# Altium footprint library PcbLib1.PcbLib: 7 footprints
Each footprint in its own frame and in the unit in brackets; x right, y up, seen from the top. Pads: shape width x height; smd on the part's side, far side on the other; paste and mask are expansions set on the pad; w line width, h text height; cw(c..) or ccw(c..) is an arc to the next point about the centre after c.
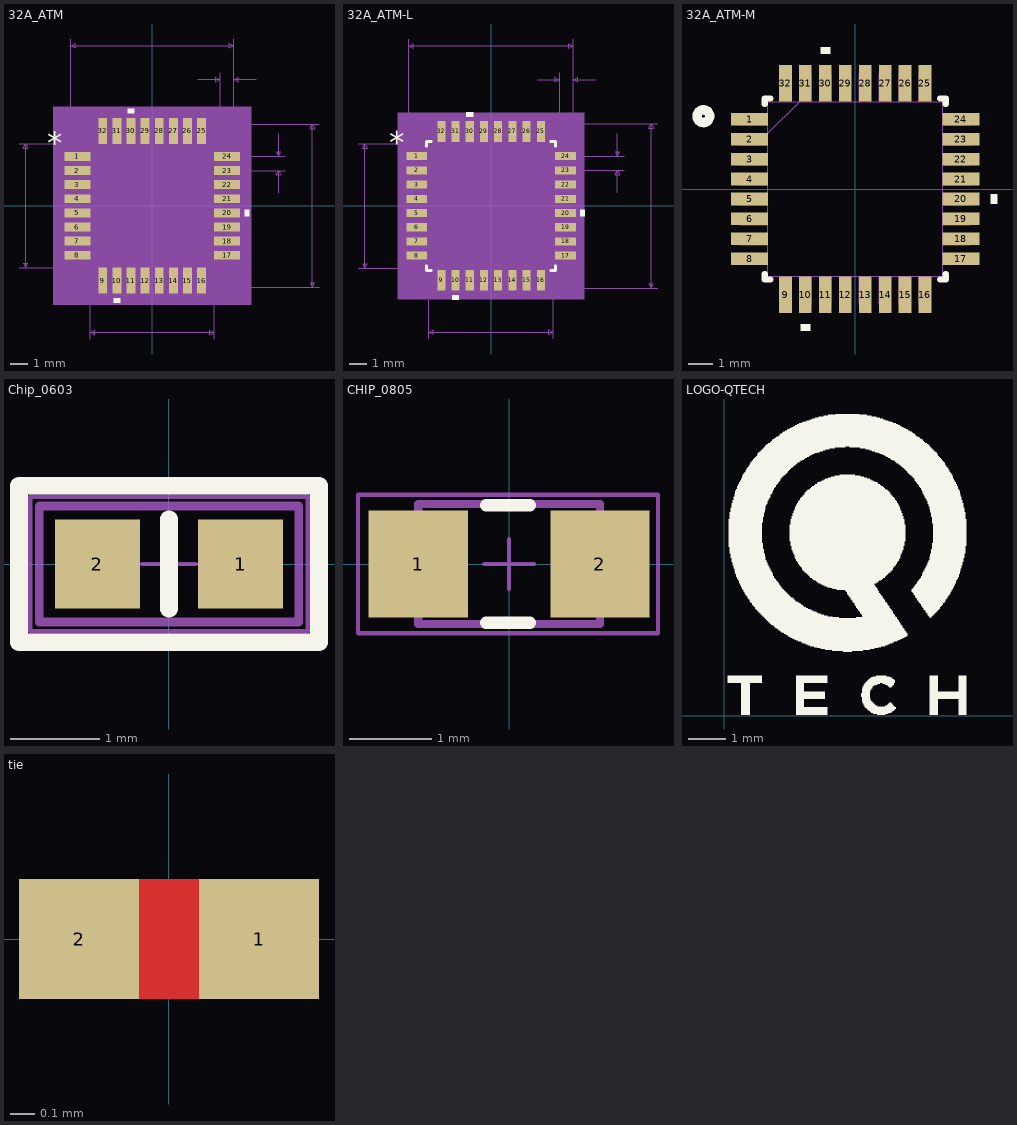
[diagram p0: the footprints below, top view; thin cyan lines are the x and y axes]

## 32A_ATM [mil]
pads (32):
  rect 58x20 smd paste+0 mask+0: 1(-167,110.24) 2(-167,78.74) 3(-167,47.24) 4(-167,15.75) 5(-167,-15.75) 6(-167,-47.24) 7(-167,-78.74) 8(-167,-110.24) 17(167,-110.24) 18(167,-78.74) 19(167,-47.24) 20(167,-15.75) 21(167,15.75) 22(167,47.24) 23(167,78.74) 24(167,110.24)
  rect 20x58 smd paste+0 mask+0: 9(-110.24,-167) 10(-78.74,-167) 11(-47.24,-167) 12(-15.75,-167) 13(15.75,-167) 14(47.24,-167) 15(78.74,-167) 16(110.24,-167) 25(110.24,167) 26(78.74,167) 27(47.24,167) 28(15.75,167) 29(-15.75,167) 30(-47.24,167) 31(-78.74,167) 32(-110.24,167)
Top Overlay:
  region: -71.24,-206 -86.24,-206 -86.24,-216 -71.24,-216
  region: 206,-8.25 216,-8.25 216,-23.25 206,-23.25
  region: -39.74,206 -54.74,206 -54.74,216 -39.74,216
  text "*" at -233.5,115.98 h50
Mechanical 5:
  region: 221,-221 -221,-221 -221,221 221,221
Mechanical 7:
  lines w1: -297,-138 -110.24,-138 ; -297,138 -110.24,138 ; -182,110.24 -182,372 ; -138,-297 -138,-110.24 ; 102,282 152,282 ; 110.24,-182 372,-182 ; 110.24,182 372,182 ; 138,-297 138,-110.24 ; 152,110.24 152,297 ; 167,78.74 297,78.74 ; 167,110.24 297,110.24 ; 182,297 182,110.24 182,372 ; 232,282 182,282 ; 282,28.74 282,78.74 ; 282,160.24 282,110.24 ; -282,-138 -282,138 ; -282,-138 -287,-128 -277,-128 -282,-138 ; -282,138 -287,128 -277,128 -282,138 ; -182,357 182,357 ; -182,357 -172,362 -172,352 -182,357 ; -138,-282 138,-282 ; -138,-282 -128,-277 -128,-287 -138,-282 ; 138,-282 128,-277 128,-287 138,-282 ; 152,282 142,287 142,277 152,282 ; 182,282 192,287 192,277 182,282 ; 182,357 172,362 172,352 182,357 ; 282,78.74 277,68.74 287,68.74 282,78.74 ; 282,110.24 277,120.24 287,120.24 282,110.24 ; 357,-182 357,182 ; 357,-182 352,-172 362,-172 357,-182 ; 357,182 352,172 362,172 357,182
  text "Default Horiz Padstyle: RX20Y58D0T" at -425,-457 h50
  text "Default Vert Padstyle: RX20Y58D0T" at -412.5,-507 h50
  text "0.031in/0.8mm" at 302,81.99 h25
  text "0.03in/0.762mm" at 79.5,302 h25
  text "0.364in/9.246mm" at -93.75,377 h25
  text "0.364in/9.246mm" at 377,-12.5 h25
  text "0.276in/7.01mm" at -87.5,-327 h25
  text "0.276in/7.01mm" at -477,-12.5 h25
Mechanical 13:
  lines w1: -138,88 -88,138 ; -182,-119.24 -182,-101.24 -138,-101.24 -138,-119.24 -182,-119.24 ; -182,-87.74 -182,-69.74 -138,-69.74 -138,-87.74 -182,-87.74 ; -182,-56.24 -182,-38.24 -138,-38.24 -138,-56.24 -182,-56.24 ; -182,-24.75 -182,-6.75 -138,-6.75 -138,-24.75 -182,-24.75 ; -182,6.75 -182,24.75 -138,24.75 -138,6.75 -182,6.75 ; -182,38.24 -182,56.24 -138,56.24 -138,38.24 -182,38.24 ; -182,69.74 -182,87.74 -138,87.74 -138,69.74 -182,69.74 ; -182,101.24 -182,119.24 -138,119.24 -138,101.24 -182,101.24 ; -138,-138 138,-138 138,138 -138,138 -138,-138 ; -119.24,-182 -119.24,-138 -101.24,-138 -101.24,-182 -119.24,-182 ; -119.24,138 -101.24,138 -101.24,182 -119.24,182 -119.24,138 ; -87.74,-182 -87.74,-138 -69.74,-138 -69.74,-182 -87.74,-182 ; -87.74,138 -69.74,138 -69.74,182 -87.74,182 -87.74,138 ; -56.24,-182 -56.24,-138 -38.24,-138 -38.24,-182 -56.24,-182 ; -56.24,138 -38.24,138 -38.24,182 -56.24,182 -56.24,138 ; -24.75,-182 -24.75,-138 -6.75,-138 -6.75,-182 -24.75,-182 ; -24.75,138 -6.75,138 -6.75,182 -24.75,182 -24.75,138 ; 6.75,-182 6.75,-138 24.75,-138 24.75,-182 6.75,-182 ; 6.75,138 24.75,138 24.75,182 6.75,182 6.75,138 ; 38.24,-182 38.24,-138 56.24,-138 56.24,-182 38.24,-182 ; 38.24,138 56.24,138 56.24,182 38.24,182 38.24,138 ; 69.74,-182 69.74,-138 87.74,-138 87.74,-182 69.74,-182 ; 69.74,138 87.74,138 87.74,182 69.74,182 69.74,138 ; 101.24,-182 101.24,-138 119.24,-138 119.24,-182 101.24,-182 ; 101.24,138 119.24,138 119.24,182 101.24,182 101.24,138 ; 138,-119.24 138,-101.24 182,-101.24 182,-119.24 138,-119.24 ; 138,-87.74 138,-69.74 182,-69.74 182,-87.74 138,-87.74 ; 138,-56.24 138,-38.24 182,-38.24 182,-56.24 138,-56.24 ; 138,-24.75 138,-6.75 182,-6.75 182,-24.75 138,-24.75 ; 138,6.75 138,24.75 182,24.75 182,6.75 138,6.75 ; 138,38.24 138,56.24 182,56.24 182,38.24 138,38.24 ; 138,69.74 138,87.74 182,87.74 182,69.74 138,69.74 ; 138,101.24 138,119.24 182,119.24 182,101.24 138,101.24
  text "*" at -130.5,85.98 h50
Mechanical 15:
  region: -130.24,-148 -148,-148 -148,-130.24 -206,-130.24 -206,130.24 -148,130.24 -148,148 -130.24,148 -130.24,206 130.24,206 130.24,148 148,148 148,130.24 206,130.24 206,-130.24 148,-130.24 148,-148 130.24,-148 130.24,-206 -130.24,-206
  lines w6: -206,-130.24 -148,-130.24 -148,-148 -130.24,-148 -130.24,-206 130.24,-206 130.24,-148 148,-148 148,-130.24 206,-130.24 206,130.24 148,130.24 148,148 130.24,148 130.24,206 -130.24,206 -130.24,148 -148,148 -148,130.24 -206,130.24 -206,-130.24
3D body: height 10, standoff 0, extent 0,0 10,10

## 32A_ATM-L [mil]
pads (32):
  rect 46x18 smd: 1(-165,110.24) 2(-165,78.74) 3(-165,47.24) 4(-165,15.75) 5(-165,-15.75) 6(-165,-47.24) 7(-165,-78.74) 8(-165,-110.24) 17(165,-110.24) 18(165,-78.74) 19(165,-47.24) 20(165,-15.75) 21(165,15.75) 22(165,47.24) 23(165,78.74) 24(165,110.24)
  rect 18x46 smd: 9(-110.24,-165) 10(-78.74,-165) 11(-47.24,-165) 12(-15.75,-165) 13(15.75,-165) 14(47.24,-165) 15(78.74,-165) 16(110.24,-165) 25(110.24,165) 26(78.74,165) 27(47.24,165) 28(15.75,165) 29(-15.75,165) 30(-47.24,165) 31(-78.74,165) 32(-110.24,165)
Top Overlay:
  region: -71.24,-198 -86.24,-198 -86.24,-208 -71.24,-208
  region: 198,-8.25 208,-8.25 208,-23.25 198,-23.25
  region: -39.74,198 -54.74,198 -54.74,208 -39.74,208
  lines w6: -143,-132.34 -143,-143 -132.34,-143 ; -143,132.34 -143,143 -132.34,143 ; 132.34,-143 143,-143 143,-132.34 ; 132.34,143 143,143 143,132.34
  text "*" at -225.5,115.98 h50
Mechanical 5:
  region: 207,-207 -207,-207 -207,207 207,207
Mechanical 7:
  lines w1: -295,-138 -110.24,-138 ; -295,138 -110.24,138 ; -182,110.24 -182,370 ; -138,-295 -138,-110.24 ; 102,280 152,280 ; 110.24,-182 370,-182 ; 110.24,182 370,182 ; 138,-295 138,-110.24 ; 152,110.24 152,295 ; 165,78.74 295,78.74 ; 165,110.24 295,110.24 ; 182,295 182,110.24 182,370 ; 232,280 182,280 ; 280,28.74 280,78.74 ; 280,160.24 280,110.24 ; -280,-138 -280,138 ; -280,-138 -285,-128 -275,-128 -280,-138 ; -280,138 -285,128 -275,128 -280,138 ; -182,355 182,355 ; -182,355 -172,360 -172,350 -182,355 ; -138,-280 138,-280 ; -138,-280 -128,-275 -128,-285 -138,-280 ; 138,-280 128,-275 128,-285 138,-280 ; 152,280 142,285 142,275 152,280 ; 182,280 192,285 192,275 182,280 ; 182,355 172,360 172,350 182,355 ; 280,78.74 275,68.74 285,68.74 280,78.74 ; 280,110.24 275,120.24 285,120.24 280,110.24 ; 355,-182 355,182 ; 355,-182 350,-172 360,-172 355,-182 ; 355,182 350,172 360,172 355,182
  text "Default Horiz Padstyle: RX18Y46D0T" at -425,-455 h50
  text "Default Vert Padstyle: RX18Y46D0T" at -412.5,-505 h50
  text "0.031in/0.8mm" at 300,81.99 h25
  text "0.03in/0.762mm" at 79.5,300 h25
  text "0.364in/9.246mm" at -93.75,375 h25
  text "0.364in/9.246mm" at 375,-12.5 h25
  text "0.276in/7.01mm" at -87.5,-325 h25
  text "0.276in/7.01mm" at -475,-12.5 h25
Mechanical 13:
  lines w1: -138,88 -88,138 ; -182,-119.24 -182,-101.24 -138,-101.24 -138,-119.24 -182,-119.24 ; -182,-87.74 -182,-69.74 -138,-69.74 -138,-87.74 -182,-87.74 ; -182,-56.24 -182,-38.24 -138,-38.24 -138,-56.24 -182,-56.24 ; -182,-24.75 -182,-6.75 -138,-6.75 -138,-24.75 -182,-24.75 ; -182,6.75 -182,24.75 -138,24.75 -138,6.75 -182,6.75 ; -182,38.24 -182,56.24 -138,56.24 -138,38.24 -182,38.24 ; -182,69.74 -182,87.74 -138,87.74 -138,69.74 -182,69.74 ; -182,101.24 -182,119.24 -138,119.24 -138,101.24 -182,101.24 ; -138,-138 138,-138 138,138 -138,138 -138,-138 ; -119.24,-182 -119.24,-138 -101.24,-138 -101.24,-182 -119.24,-182 ; -119.24,138 -101.24,138 -101.24,182 -119.24,182 -119.24,138 ; -87.74,-182 -87.74,-138 -69.74,-138 -69.74,-182 -87.74,-182 ; -87.74,138 -69.74,138 -69.74,182 -87.74,182 -87.74,138 ; -56.24,-182 -56.24,-138 -38.24,-138 -38.24,-182 -56.24,-182 ; -56.24,138 -38.24,138 -38.24,182 -56.24,182 -56.24,138 ; -24.75,-182 -24.75,-138 -6.75,-138 -6.75,-182 -24.75,-182 ; -24.75,138 -6.75,138 -6.75,182 -24.75,182 -24.75,138 ; 6.75,-182 6.75,-138 24.75,-138 24.75,-182 6.75,-182 ; 6.75,138 24.75,138 24.75,182 6.75,182 6.75,138 ; 38.24,-182 38.24,-138 56.24,-138 56.24,-182 38.24,-182 ; 38.24,138 56.24,138 56.24,182 38.24,182 38.24,138 ; 69.74,-182 69.74,-138 87.74,-138 87.74,-182 69.74,-182 ; 69.74,138 87.74,138 87.74,182 69.74,182 69.74,138 ; 101.24,-182 101.24,-138 119.24,-138 119.24,-182 101.24,-182 ; 101.24,138 119.24,138 119.24,182 101.24,182 101.24,138 ; 138,-119.24 138,-101.24 182,-101.24 182,-119.24 138,-119.24 ; 138,-87.74 138,-69.74 182,-69.74 182,-87.74 138,-87.74 ; 138,-56.24 138,-38.24 182,-38.24 182,-56.24 138,-56.24 ; 138,-24.75 138,-6.75 182,-6.75 182,-24.75 138,-24.75 ; 138,6.75 138,24.75 182,24.75 182,6.75 138,6.75 ; 138,38.24 138,56.24 182,56.24 182,38.24 138,38.24 ; 138,69.74 138,87.74 182,87.74 182,69.74 138,69.74 ; 138,101.24 138,119.24 182,119.24 182,101.24 138,101.24
  text "*" at -134.5,85.98 h50
Mechanical 15:
  region: -118.24,-142 -142,-142 -142,-118.24 -192,-118.24 -192,118.24 -142,118.24 -142,142 -118.24,142 -118.24,192 118.24,192 118.24,142 142,142 142,118.24 192,118.24 192,-118.24 142,-118.24 142,-142 118.24,-142 118.24,-192 -118.24,-192
  lines w6: -192,-118.24 -142,-118.24 -142,-142 -118.24,-142 -118.24,-192 118.24,-192 118.24,-142 142,-142 142,-118.24 192,-118.24 192,118.24 142,118.24 142,142 118.24,142 118.24,192 -118.24,192 -118.24,142 -142,142 -142,118.24 -192,118.24 -192,-118.24
3D body: height 10, standoff 0, extent 0,0 10,10

## 32A_ATM-M [mil]
pads (32):
  rect 58x20 smd paste+0 mask+5: 1(-167,110.24) 2(-167,78.74) 3(-167,47.24) 4(-167,15.75) 5(-167,-15.75) 6(-167,-47.24) 7(-167,-78.74) 8(-167,-110.24) 17(167,-110.24) 18(167,-78.74) 19(167,-47.24) 20(167,-15.75) 21(167,15.75) 22(167,47.24) 23(167,78.74) 24(167,110.24)
  rect 20x58 smd paste+0 mask+5: 9(-110.24,-167) 10(-78.74,-167) 11(-47.24,-167) 12(-15.75,-167) 13(15.75,-167) 14(47.24,-167) 15(78.74,-167) 16(110.24,-167) 25(110.24,167) 26(78.74,167) 27(47.24,167) 28(15.75,167) 29(-15.75,167) 30(-47.24,167) 31(-78.74,167) 32(-110.24,167)
Top Overlay:
  circle w15: c-240,115 r10
  region: -39.74,214 -54.74,214 -54.74,224 -39.74,224
  region: 214,-8.25 224,-8.25 224,-23.25 214,-23.25
  region: -71.24,-214 -86.24,-214 -86.24,-224 -71.24,-224
  lines w10: -143,-134.34 -143,-143 -134.34,-143 ; -143,134.34 -143,143 -134.34,143 ; 134.34,-143 143,-143 143,-134.34 ; 134.34,143 143,143 143,134.34
Mechanical 15:
  lines w1.97: -138,88 -88,138 ; -182,-119.24 -182,-101.24 -138,-101.24 -138,-119.24 -182,-119.24 ; -182,-87.74 -182,-69.74 -138,-69.74 -138,-87.74 -182,-87.74 ; -182,-56.24 -182,-38.24 -138,-38.24 -138,-56.24 -182,-56.24 ; -182,-24.75 -182,-6.75 -138,-6.75 -138,-24.75 -182,-24.75 ; -182,6.75 -182,24.75 -138,24.75 -138,6.75 -182,6.75 ; -182,38.24 -182,56.24 -138,56.24 -138,38.24 -182,38.24 ; -182,69.74 -182,87.74 -138,87.74 -138,69.74 -182,69.74 ; -182,101.24 -182,119.24 -138,119.24 -138,101.24 -182,101.24 ; -138,-138 -138,138 138,138 138,-138 -138,-138 ; -119.24,-182 -101.24,-182 -101.24,-138 -119.24,-138 -119.24,-182 ; -119.24,138 -101.24,138 -101.24,182 -119.24,182 -119.24,138 ; -87.74,-182 -87.74,-138 -69.74,-138 -69.74,-182 -87.74,-182 ; -87.74,138 -87.74,182 -69.74,182 -69.74,138 -87.74,138 ; -56.24,-182 -38.24,-182 -38.24,-138 -56.24,-138 -56.24,-182 ; -56.24,138 -38.24,138 -38.24,182 -56.24,182 -56.24,138 ; -24.75,-182 -6.75,-182 -6.75,-138 -24.75,-138 -24.75,-182 ; -24.75,138 -6.75,138 -6.75,182 -24.75,182 -24.75,138 ; 6.75,-182 24.75,-182 24.75,-138 6.75,-138 6.75,-182 ; 6.75,138 24.75,138 24.75,182 6.75,182 6.75,138 ; 38.24,-182 56.24,-182 56.24,-138 38.24,-138 38.24,-182 ; 38.24,138 56.24,138 56.24,182 38.24,182 38.24,138 ; 69.74,-182 69.74,-138 87.74,-138 87.74,-182 69.74,-182 ; 69.74,138 69.74,182 87.74,182 87.74,138 69.74,138 ; 101.24,-182 119.24,-182 119.24,-138 101.24,-138 101.24,-182 ; 101.24,138 119.24,138 119.24,182 101.24,182 101.24,138 ; 138,-119.24 138,-101.24 182,-101.24 182,-119.24 138,-119.24 ; 138,-87.74 138,-69.74 182,-69.74 182,-87.74 138,-87.74 ; 138,-56.24 138,-38.24 182,-38.24 182,-56.24 138,-56.24 ; 138,-24.75 138,-6.75 182,-6.75 182,-24.75 138,-24.75 ; 138,6.75 138,24.75 182,24.75 182,6.75 138,6.75 ; 138,38.24 138,56.24 182,56.24 182,38.24 138,38.24 ; 138,69.74 138,87.74 182,87.74 182,69.74 138,69.74 ; 138,101.24 138,119.24 182,119.24 182,101.24 138,101.24
3D body: height 10, standoff 0, extent 0,0 10,10
3D body "32A_ATM.step": height 47.09, standoff 0, extent -182,-182 182.01,182.01

## Chip_0603 [mm]
height 0.55
pads (2):
  rect 0.95x1 smd: 1(0.8,0) 2(-0.8,0)
Top Overlay:
  lines w0.2: 0,-0.5 0,0.5 ; -1.676,-0.875 -1.676,0.875 1.676,0.875 1.676,-0.875 -1.676,-0.875
Mechanical 9:
  lines w0.1: -1.45,-0.65 -1.45,0.65 1.45,0.65 1.45,-0.65 -1.45,-0.65
Mechanical 15:
  lines w0.05: -0.3,0 0.3,0 ; 0,-0.3 0,0.3 ; -1.55,-0.75 -1.55,0.75 1.55,0.75 1.55,-0.75 -1.55,-0.75
3D body "INDC1608X95.STEP": height 0.95, standoff 0, extent -0.8,-0.4 0.8,0.4

## CHIP_0805 [mm]
height 1.45
pads (2):
  rect 1.2x1.3 smd mask+0.064: 1(-1.1,0) 2(1.1,0)
Top Overlay:
  lines w0.15: -0.279,-0.711 0.254,-0.711 ; -0.279,0.711 0.254,0.711
Mechanical 9:
  lines w0.1: -1.1,-0.725 1.1,-0.725 1.1,0.725 -1.1,0.725 -1.1,-0.725
Mechanical 15:
  lines w0.05: -0.3,0 0.3,0 ; 0,-0.3 0,0.3 ; -1.829,-0.838 1.803,-0.838 1.803,0.838 -1.829,0.838 -1.829,-0.838
3D body "CAPC_0805.STEP": height 0.88, standoff 0, extent -1,-0.625 1,0.625

## LOGO-QTECH [mil]
Top Overlay:
  drawing of 802 lines, arcs and shapes, not listed

## tie [mm]
pads (2):
  rect 0.5x0.5 smd paste-1 mask+0.102: 1(0.375,0) 2(-0.375,0)
Top Layer:
  rectangle: -0.625,-0.25 0.625,0.25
